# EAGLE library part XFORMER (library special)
TRANSFORMER 2 x primary, 2 x secondary
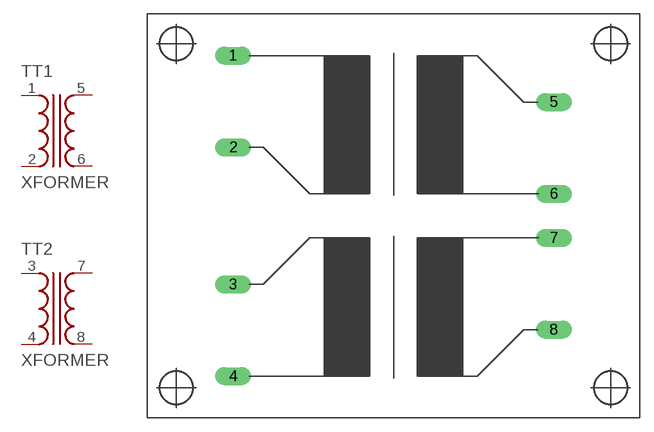
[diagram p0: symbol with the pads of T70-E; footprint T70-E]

Designator prefix T; gates T1=XFORMER T2=XFORMER

## XFORMER  [T70-E]
1  T1:P1  pas
2  T1:P2  pas
3  T2:P1  pas
4  T2:P2  pas
5  T1:S1  pas
6  T1:S2  pas
7  T2:S1  pas
8  T2:S2  pas

## Footprint T70-E (pad centres in mm)
TRANSFORMER 2 x primary 2 x secondary
drill 1.321 long: 1 -17.526,17.526; 2 -17.526,7.493; 3 -17.526,-7.493; 4 -17.526,-17.526; 5 17.526,12.446; 6 17.526,2.413; 7 17.526,-2.413; 8 17.526,-12.446
hole 3.708 at 23.749,18.796
hole 3.708 at 23.749,-18.796
hole 3.708 at -23.749,-18.796
hole 3.708 at -23.749,18.796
